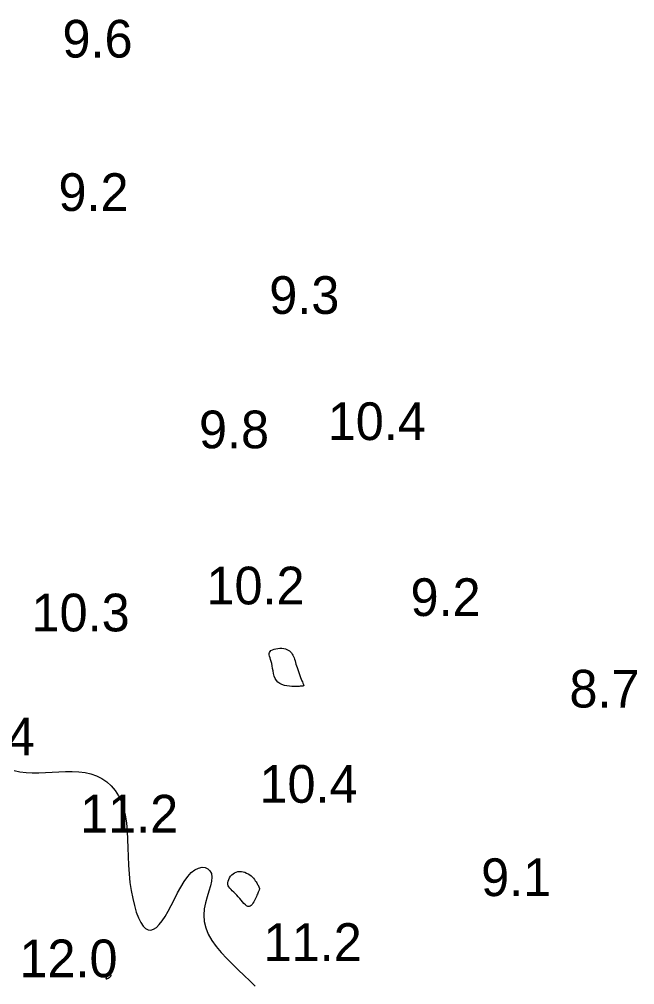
# Model space of a CAD drawing. Extents: x 3040093 to 3056816, y 408076 to 509144.
# Drawn here: x 3044608.9 to 3044690.5, y 435539.2 to 435667.2 of the extents above; entities that cross this region are included whole.
import ezdxf

# ---------------------------------------------------------------- set-up
doc = ezdxf.new("R2010")
doc.units = 0
doc.layers.add('V-CHAN-CONT-EL12-1112', color=7, linetype='Continuous')
doc.layers.add('V-TOPO-SOUN-0810', color=7, linetype='Continuous')

msp = doc.modelspace()

# ---------------------------------------------------------------- linework, layer by layer
at = {"layer": 'V-CHAN-CONT-EL12-1112'}
for points in [[(3044646.44, 435578.82), (3044646.39, 435578.81), (3044646.33, 435578.81), (3044646.25, 435578.8), (3044646.14, 435578.8), (3044646, 435578.79), (3044645.82, 435578.79), (3044645.6, 435578.79), (3044645.33, 435578.79), (3044645.03, 435578.79), (3044644.71, 435578.82), (3044644.37, 435578.86), (3044644.04, 435578.92), (3044643.72, 435579.02), (3044643.43, 435579.16), (3044643.18, 435579.35), (3044642.98, 435579.58), (3044642.83, 435579.85), (3044642.71, 435580.16), (3044642.62, 435580.49), (3044642.55, 435580.83), (3044642.49, 435581.17), (3044642.43, 435581.5), (3044642.37, 435581.81), (3044642.3, 435582.09), (3044642.22, 435582.35), (3044642.14, 435582.58), (3044642.08, 435582.79), (3044642.04, 435582.97), (3044642.03, 435583.14), (3044642.06, 435583.28), (3044642.14, 435583.41), (3044642.27, 435583.53), (3044642.45, 435583.63), (3044642.67, 435583.71), (3044642.92, 435583.77), (3044643.18, 435583.82), (3044643.45, 435583.84), (3044643.71, 435583.84), (3044643.96, 435583.81), (3044644.18, 435583.77), (3044644.38, 435583.69), (3044644.56, 435583.6), (3044644.72, 435583.49), (3044644.85, 435583.36), (3044644.98, 435583.22), (3044645.08, 435583.07), (3044645.18, 435582.91), (3044645.26, 435582.74), (3044645.33, 435582.56), (3044645.39, 435582.38), (3044645.46, 435582.18), (3044645.52, 435581.97), (3044645.58, 435581.75), (3044645.65, 435581.52), (3044645.73, 435581.28), (3044645.81, 435581.02), (3044645.91, 435580.76), (3044646, 435580.49), (3044646.1, 435580.23), (3044646.2, 435579.98), (3044646.29, 435579.75), (3044646.37, 435579.54), (3044646.44, 435579.37), (3044646.49, 435579.23), (3044646.53, 435579.13), (3044646.56, 435579.05), (3044646.58, 435579), (3044646.59, 435578.97), (3044646.6, 435578.95), (3044646.6, 435578.94), (3044646.6, 435578.93), (3044646.61, 435578.93), (3044646.61, 435578.93), (3044646.61, 435578.92), (3044646.61, 435578.92), (3044646.61, 435578.92), (3044646.61, 435578.91), (3044646.61, 435578.91), (3044646.61, 435578.91), (3044646.61, 435578.9), (3044646.61, 435578.9), (3044646.61, 435578.9), (3044646.61, 435578.89), (3044646.61, 435578.89), (3044646.61, 435578.89), (3044646.6, 435578.88), (3044646.6, 435578.88), (3044646.6, 435578.88), (3044646.6, 435578.88), (3044646.6, 435578.87), (3044646.6, 435578.87), (3044646.59, 435578.87), (3044646.59, 435578.86), (3044646.59, 435578.86), (3044646.58, 435578.86), (3044646.58, 435578.85), (3044646.57, 435578.85), (3044646.56, 435578.85), (3044646.55, 435578.84), (3044646.54, 435578.84), (3044646.52, 435578.83), (3044646.5, 435578.83), (3044646.47, 435578.82)], [(3044640.08, 435550.38), (3044639.98, 435550.2), (3044639.88, 435550.02), (3044639.76, 435549.87), (3044639.63, 435549.74), (3044639.5, 435549.65), (3044639.36, 435549.61), (3044639.21, 435549.62), (3044639.04, 435549.7), (3044638.87, 435549.83), (3044638.69, 435550), (3044638.51, 435550.2), (3044638.32, 435550.43), (3044638.13, 435550.66), (3044637.93, 435550.9), (3044637.73, 435551.12), (3044637.52, 435551.33), (3044637.33, 435551.51), (3044637.14, 435551.69), (3044636.97, 435551.85), (3044636.82, 435552.02), (3044636.7, 435552.19), (3044636.61, 435552.36), (3044636.56, 435552.55), (3044636.56, 435552.75), (3044636.59, 435552.97), (3044636.66, 435553.18), (3044636.77, 435553.4), (3044636.9, 435553.6), (3044637.06, 435553.79), (3044637.25, 435553.95), (3044637.45, 435554.08), (3044637.66, 435554.17), (3044637.89, 435554.23), (3044638.12, 435554.25), (3044638.36, 435554.24), (3044638.59, 435554.2), (3044638.82, 435554.14), (3044639.04, 435554.04), (3044639.25, 435553.93), (3044639.45, 435553.8), (3044639.63, 435553.65), (3044639.8, 435553.5), (3044639.94, 435553.34), (3044640.08, 435553.17), (3044640.19, 435553.02), (3044640.29, 435552.87), (3044640.38, 435552.74), (3044640.45, 435552.62), (3044640.5, 435552.53), (3044640.55, 435552.44), (3044640.58, 435552.38), (3044640.6, 435552.32), (3044640.62, 435552.27), (3044640.64, 435552.23), (3044640.65, 435552.2), (3044640.67, 435552.16), (3044640.68, 435552.14), (3044640.69, 435552.11), (3044640.71, 435552.09), (3044640.72, 435552.06), (3044640.73, 435552.04), (3044640.74, 435552.03), (3044640.75, 435552.01), (3044640.75, 435551.99), (3044640.75, 435551.97), (3044640.75, 435551.95), (3044640.74, 435551.92), (3044640.73, 435551.88), (3044640.72, 435551.83), (3044640.69, 435551.77), (3044640.67, 435551.69), (3044640.63, 435551.6), (3044640.59, 435551.49), (3044640.54, 435551.37), (3044640.48, 435551.23), (3044640.41, 435551.08), (3044640.34, 435550.92), (3044640.26, 435550.75), (3044640.18, 435550.57)], [(3044621.05, 435540.39), (3044621.06, 435540.43), (3044621.06, 435540.48), (3044621.06, 435540.51), (3044621.05, 435540.55), (3044621.03, 435540.57), (3044621, 435540.59), (3044620.97, 435540.6), (3044620.93, 435540.6), (3044620.88, 435540.59), (3044620.83, 435540.57), (3044620.77, 435540.54), (3044620.72, 435540.5), (3044620.67, 435540.46), (3044620.62, 435540.41), (3044620.57, 435540.36), (3044620.52, 435540.31), (3044620.49, 435540.26), (3044620.46, 435540.21), (3044620.43, 435540.16), (3044620.41, 435540.12), (3044620.4, 435540.08), (3044620.39, 435540.04), (3044620.4, 435540.02), (3044620.41, 435540), (3044620.43, 435540), (3044620.45, 435540), (3044620.48, 435540), (3044620.52, 435540.02), (3044620.56, 435540.03), (3044620.61, 435540.05), (3044620.66, 435540.08), (3044620.71, 435540.1), (3044620.76, 435540.13), (3044620.81, 435540.17), (3044620.87, 435540.2), (3044620.91, 435540.23), (3044620.96, 435540.27), (3044620.99, 435540.31), (3044621.02, 435540.35)]]:
    msp.add_lwpolyline(points, close=True, dxfattribs=at)
msp.add_lwpolyline([(3044608.23, 435567.63), (3044608.99, 435567.46), (3044609.79, 435567.36), (3044610.62, 435567.31), (3044611.48, 435567.31), (3044612.37, 435567.35), (3044613.26, 435567.4), (3044614.15, 435567.45), (3044615.04, 435567.49), (3044615.92, 435567.5), (3044616.78, 435567.47), (3044617.61, 435567.37), (3044618.4, 435567.2), (3044619.15, 435566.94), (3044619.85, 435566.58), (3044620.5, 435566.14), (3044621.08, 435565.61), (3044621.6, 435564.99), (3044622.05, 435564.29), (3044622.43, 435563.5), (3044622.73, 435562.64), (3044622.95, 435561.69), (3044623.1, 435560.68), (3044623.19, 435559.61), (3044623.25, 435558.5), (3044623.29, 435557.37), (3044623.33, 435556.21), (3044623.38, 435555.06), (3044623.46, 435553.91), (3044623.57, 435552.79), (3044623.73, 435551.7), (3044623.93, 435550.67), (3044624.16, 435549.72), (3044624.41, 435548.86), (3044624.69, 435548.1), (3044624.99, 435547.48), (3044625.31, 435546.99), (3044625.64, 435546.67), (3044625.98, 435546.49), (3044626.34, 435546.46), (3044626.7, 435546.58), (3044627.07, 435546.82), (3044627.45, 435547.19), (3044627.84, 435547.68), (3044628.24, 435548.28), (3044628.64, 435548.98), (3044629.05, 435549.75), (3044629.46, 435550.57), (3044629.89, 435551.39), (3044630.32, 435552.18), (3044630.77, 435552.92), (3044631.23, 435553.57), (3044631.7, 435554.09), (3044632.19, 435554.47), (3044632.67, 435554.7), (3044633.13, 435554.8), (3044633.54, 435554.76), (3044633.9, 435554.61), (3044634.18, 435554.34), (3044634.37, 435553.97), (3044634.44, 435553.5), (3044634.39, 435552.95), (3044634.23, 435552.32), (3044634.03, 435551.63), (3044633.8, 435550.88), (3044633.58, 435550.09), (3044633.42, 435549.28), (3044633.35, 435548.44), (3044633.4, 435547.6), (3044633.61, 435546.76), (3044633.96, 435545.93), (3044634.44, 435545.1), (3044635.02, 435544.29), (3044635.68, 435543.49), (3044636.4, 435542.71), (3044637.15, 435541.93), (3044637.93, 435541.18), (3044638.71, 435540.45), (3044639.46, 435539.73), (3044640.18, 435539.02)], dxfattribs=at)

# ---------------------------------------------------------------- texts
at = {"layer": 'V-TOPO-SOUN-0810'}
for s, p in [('9.6', (3044614.62, 435662.17)), ('9.2', (3044614.09, 435641.83)), ('9.3', (3044642.04, 435628.18)), ('10.4 ', (3044649.79, 435611.45)), ('9.8', (3044632.72, 435610.36)), ('10.2 ', (3044633.71, 435589.66)), ('9.2', (3044660.77, 435588.12)), ('10.3 ', (3044610.52, 435586.08)), ('8.7', (3044681.84, 435575.98)), ('11.4 ', (3044597.95, 435569.65)), ('10.4 ', (3044640.74, 435563.35)), ('11.2 ', (3044616.95, 435559.41)), ('9.1', (3044670.13, 435550.98)), ('11.2 ', (3044641.29, 435542.38)), ('12.0 ', (3044608.91, 435540.22))]:
    msp.add_text(s, height=5, dxfattribs=at).set_placement(p)

doc.saveas('drawing.dxf')
